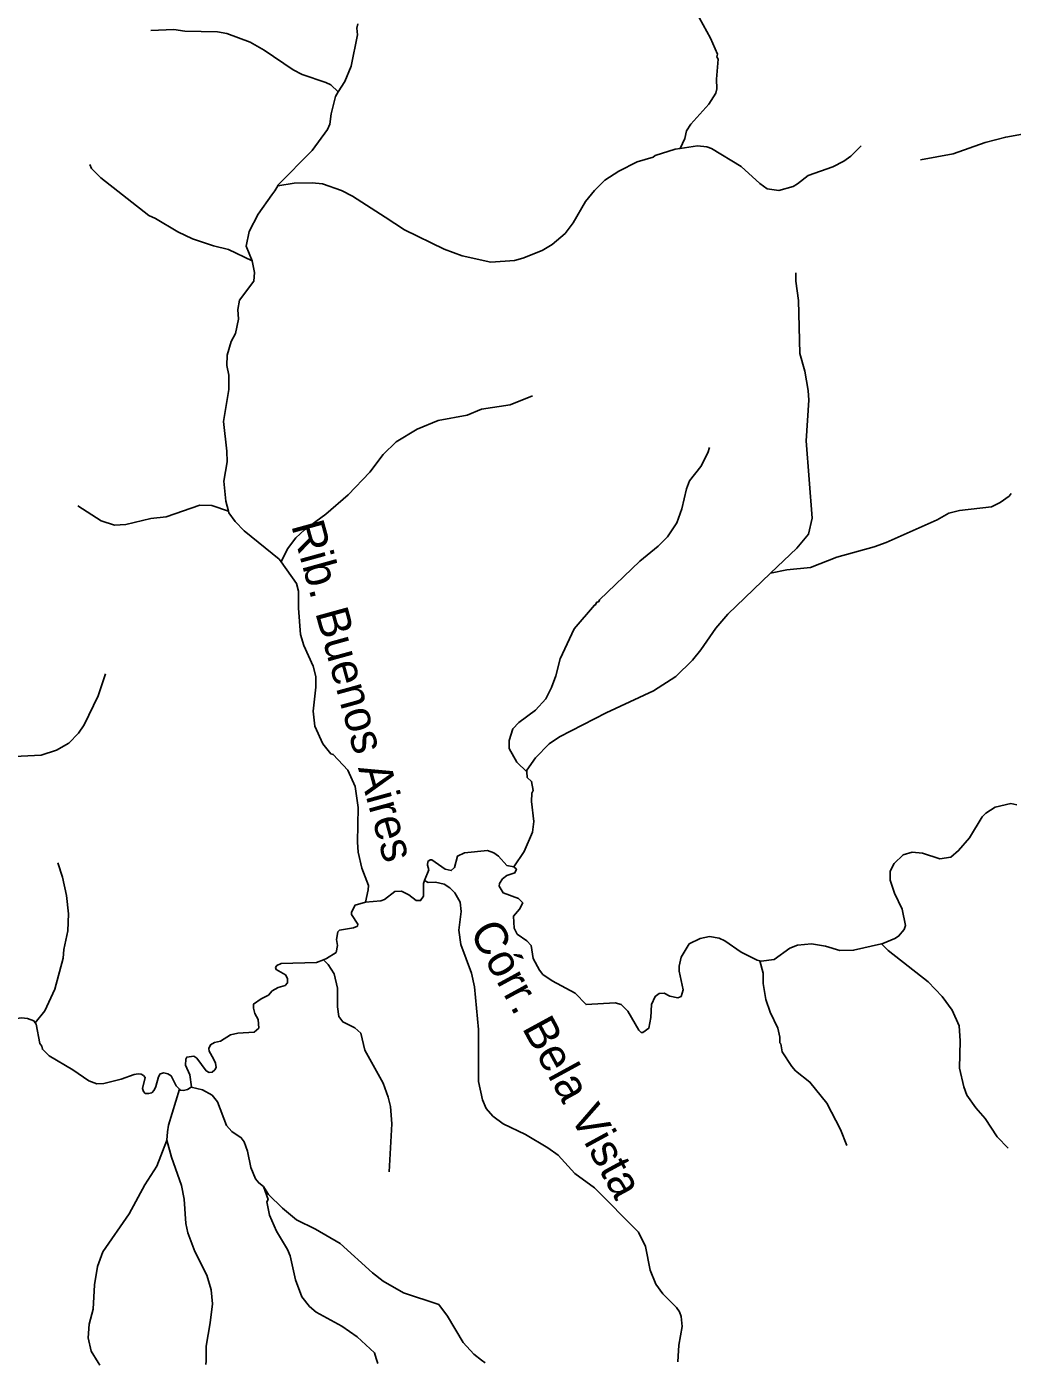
# Model space of a CAD drawing. Extents: x 280.4 to 335.6, y 8893.9 to 8949.5.
# Drawn here: x 288.06 to 294.07, y 8893.97 to 8902.11 of the extents above; entities that cross this region are included whole.
import ezdxf
from ezdxf.enums import TextEntityAlignment as Align

# ---------------------------------------------------------------- set-up
doc = ezdxf.new("R2010")
doc.units = 0
doc.header["$LTSCALE"] = 0.064
doc.layers.add('61', color=7, linetype='Continuous')
doc.layers.add('7', color=7, linetype='Continuous', lineweight=25)

msp = doc.modelspace()

# ---------------------------------------------------------------- linework, layer by layer
at = {"layer": '7'}
for points in [[(292.1026, 8902.3635), (292.1381, 8902.2072), (292.2287, 8902.0446), (292.2702, 8901.9485), (292.2673, 8901.9318), (292.2752, 8901.9178), (292.2642, 8901.7959), (292.2672, 8901.7361), (292.2606, 8901.7107), (292.2176, 8901.6432), (292.1079, 8901.5207), (292.0823, 8901.4806), (292.0711, 8901.4353), (292.0427, 8901.374)], [(290.0785, 8902.132), (290.0737, 8902.1062), (290.0781, 8902.0646), (290.0394, 8901.8751), (290.0003, 8901.7808), (289.96, 8901.718)], [(288.8188, 8902.0924), (288.9593, 8902.0974), (289.0246, 8902.0879), (289.2238, 8902.0829), (289.2805, 8902.0732), (289.4237, 8902.0206), (289.5095, 8901.9715), (289.6843, 8901.8535), (289.7411, 8901.8237), (289.885, 8901.7757), (289.9143, 8901.7605), (289.96, 8901.718)], [(289.96, 8901.718), (289.9426, 8901.691), (289.9167, 8901.5856), (289.9084, 8901.5209), (289.8939, 8901.4882), (289.8002, 8901.361), (289.5925, 8901.1493), (289.5911, 8901.1461)], [(293.5062, 8901.3053), (293.7072, 8901.3412), (293.9017, 8901.4091), (294.0265, 8901.4433), (294.1731, 8901.4679)], [(292.0427, 8901.374), (292.0132, 8901.3699), (291.8904, 8901.33), (291.8794, 8901.3204), (291.781, 8901.2914), (291.6685, 8901.2353), (291.585, 8901.1814), (291.5205, 8901.1171), (291.4672, 8901.0509), (291.3904, 8900.9214), (291.3428, 8900.8565), (291.2642, 8900.7884), (291.2027, 8900.7528), (291.0837, 8900.7054), (291.0333, 8900.6919), (290.8895, 8900.6821), (290.7152, 8900.7191), (290.605, 8900.7601), (290.3641, 8900.8791), (290.2452, 8900.9555), (290.0465, 8901.0831), (289.9803, 8901.1187), (289.8644, 8901.1587), (289.801, 8901.1651), (289.6917, 8901.1617), (289.5911, 8901.1461)], [(293.1458, 8901.3899), (293.0836, 8901.3274), (293.0397, 8901.2954), (292.9724, 8901.262), (292.8229, 8901.21), (292.7587, 8901.1575), (292.7317, 8901.143), (292.6446, 8901.1173), (292.5739, 8901.1273), (292.5288, 8901.1606), (292.415, 8901.2638), (292.2345, 8901.3731), (292.2048, 8901.3828), (292.1489, 8901.3889), (292.0427, 8901.374)], [(288.4457, 8901.2761), (288.4572, 8901.2525), (288.5135, 8901.1949), (288.805, 8900.9653), (288.8457, 8900.9479), (288.9818, 8900.8667), (289.0727, 8900.8245), (289.2003, 8900.7805), (289.2921, 8900.7578), (289.4346, 8900.6905)], [(289.5911, 8901.1461), (289.5731, 8901.1158), (289.5552, 8901.0912), (289.4719, 8900.9745), (289.4174, 8900.8676), (289.3984, 8900.7798), (289.4346, 8900.6905)], [(289.4346, 8900.6905), (289.4502, 8900.6189), (289.4458, 8900.5657), (289.3584, 8900.4501), (289.3472, 8900.3942), (289.3517, 8900.3351), (289.3348, 8900.2468), (289.3082, 8900.1977), (289.283, 8900.1143), (289.2815, 8900.0513), (289.2926, 8899.9937), (289.2942, 8899.9064), (289.2606, 8899.7122), (289.2814, 8899.5314), (289.2829, 8899.4667), (289.2639, 8899.3483), (289.2751, 8899.2267), (289.291, 8899.1653)], [(292.7486, 8900.617), (292.7471, 8900.565), (292.763, 8900.4486), (292.7712, 8900.1256), (292.8031, 8900.0175), (292.8235, 8899.9), (292.8269, 8899.8416), (292.8111, 8899.593), (292.8462, 8899.1219), (292.8256, 8899.0261), (292.7537, 8898.9409), (292.5936, 8898.7874)], [(291.1433, 8899.8671), (291.0083, 8899.8125), (290.8333, 8899.7854), (290.7463, 8899.75), (290.5681, 8899.7175), (290.441, 8899.6649), (290.3136, 8899.587), (290.2331, 8899.5098), (290.1525, 8899.4037), (290.0203, 8899.2652), (289.8851, 8899.1469), (289.7551, 8899.0513), (289.7016, 8899.0024), (289.6513, 8898.9364), (289.6117, 8898.8573)], [(292.2218, 8899.5529), (292.2122, 8899.5202), (292.1687, 8899.4379), (292.1007, 8899.3509), (292.0813, 8899.3018), (292.0529, 8899.1789), (292.0231, 8899.094), (291.9655, 8899.0098), (291.908, 8898.9523), (291.7966, 8898.86), (291.5506, 8898.6248), (291.547, 8898.6153), (291.5342, 8898.61), (291.5282, 8898.5955), (291.5208, 8898.5936), (291.3963, 8898.4479), (291.3127, 8898.2672), (291.2858, 8898.1633), (291.26, 8898.092), (291.2238, 8898.0225), (291.1615, 8897.9533), (291.0605, 8897.8791), (291.0245, 8897.8398), (291.0009, 8897.769), (291.0008, 8897.7195), (291.0483, 8897.6375), (291.1086, 8897.5779)], [(294.0587, 8899.2729), (294.0474, 8899.2571), (293.9934, 8899.2175), (293.9391, 8899.1909), (293.7456, 8899.1692), (293.6796, 8899.153), (293.6085, 8899.113), (293.2989, 8898.9751), (293.2242, 8898.9477), (292.9965, 8898.8861), (292.8371, 8898.8222), (292.692, 8898.8081), (292.5936, 8898.7874)], [(288.3732, 8899.1969), (288.5149, 8899.1056), (288.596, 8899.0797), (288.6657, 8899.0845), (288.8186, 8899.121), (288.912, 8899.1309), (289.1175, 8899.2011), (289.19, 8899.2005), (289.291, 8899.1653)], [(289.291, 8899.1653), (289.2939, 8899.1542), (289.3313, 8899.1018), (289.3868, 8899.0464), (289.5999, 8898.8738), (289.6117, 8898.8573)], [(289.6117, 8898.8573), (289.7055, 8898.7258), (289.7175, 8898.6789), (289.7181, 8898.5742), (289.7309, 8898.4144), (289.7511, 8898.3475), (289.8066, 8898.2208), (289.8235, 8898.1577), (289.8234, 8898.0938), (289.8077, 8897.9473), (289.8183, 8897.8562), (289.8664, 8897.7494), (289.9152, 8897.6884), (289.9289, 8897.6833), (290.0183, 8897.5886), (290.0638, 8897.4883)], [(292.5936, 8898.7874), (292.3344, 8898.539), (292.2613, 8898.4533), (292.1691, 8898.3214), (292.1174, 8898.2583), (292.0171, 8898.1582), (291.8802, 8898.0706), (291.5923, 8897.9377), (291.3071, 8897.7905), (291.2457, 8897.7479), (291.1616, 8897.6639), (291.1082, 8897.5875), (291.1086, 8897.5779)], [(288.541, 8898.1756), (288.4966, 8898.0414), (288.4129, 8897.8643), (288.3765, 8897.8128), (288.3176, 8897.7531), (288.2442, 8897.711), (288.1491, 8897.6791), (287.9876, 8897.6723), (287.923, 8897.6592), (287.7644, 8897.5751), (287.6662, 8897.5355), (287.6053, 8897.502), (287.5146, 8897.4319)], [(291.1086, 8897.5779), (291.1099, 8897.5441), (291.1379, 8897.5199), (291.1473, 8897.4641), (291.1385, 8897.4477), (291.1367, 8897.398), (291.1508, 8897.2753), (291.1444, 8897.2118), (291.092, 8897.0939), (291.0298, 8897.0005)], [(290.0638, 8897.4883), (290.081, 8897.362), (290.0763, 8897.1502), (290.0823, 8897.0898), (290.103, 8896.9926), (290.1434, 8896.8855), (290.1429, 8896.8602), (290.1253, 8896.7855)], [(294.0943, 8897.3777), (294.0566, 8897.3844), (293.962, 8897.3639), (293.9056, 8897.3272), (293.8826, 8897.3044), (293.8066, 8897.1769), (293.739, 8897.0987), (293.6921, 8897.0583), (293.6258, 8897.0487), (293.5203, 8897.0839), (293.4572, 8897.0901), (293.4023, 8897.0737), (293.3468, 8897.0198), (293.3229, 8896.9727), (293.3231, 8896.9192), (293.3488, 8896.8402), (293.3963, 8896.7415), (293.4156, 8896.6425)], [(291.0298, 8897.0005), (290.9879, 8897.0072), (290.9353, 8897.064), (290.9072, 8897.0856), (290.8701, 8897.0996), (290.7283, 8897.0842), (290.6861, 8897.0643), (290.668, 8896.9963), (290.6482, 8896.9769), (290.6112, 8896.9861), (290.5311, 8897.0432), (290.5197, 8897.0428), (290.5065, 8897.0317), (290.5035, 8897.0103), (290.511, 8896.9807), (290.4854, 8896.916)], [(288.252, 8897.0248), (288.2805, 8896.9359), (288.3041, 8896.8253), (288.317, 8896.7134), (288.3122, 8896.611), (288.2888, 8896.4966), (288.2849, 8896.4427), (288.2334, 8896.254), (288.173, 8896.1227), (288.1132, 8896.0501)], [(292.5286, 8896.4278), (292.5128, 8896.4313), (292.4143, 8896.4801), (292.3152, 8896.5495), (292.2807, 8896.5653), (292.2224, 8896.5752), (292.1656, 8896.5642), (292.0978, 8896.5303), (292.0496, 8896.4497), (292.0373, 8896.3944), (292.037, 8896.3649), (292.0623, 8896.2505), (292.0489, 8896.2104), (292.0298, 8896.2027), (291.981, 8896.2118), (291.945, 8896.2296), (291.9155, 8896.2278), (291.8905, 8896.2109), (291.8677, 8896.1609), (291.8638, 8896.0815), (291.8517, 8896.0168), (291.8157, 8895.9914), (291.8061, 8895.9905), (291.7902, 8896.0049), (291.7234, 8896.121), (291.6844, 8896.1612), (291.6465, 8896.1722), (291.4695, 8896.1613), (291.4026, 8896.2303), (291.2623, 8896.3053), (291.2072, 8896.3435), (291.1858, 8896.3704), (291.1484, 8896.4425), (291.135, 8896.5216), (291.1084, 8896.5488), (291.0508, 8896.5908), (291.031, 8896.6271), (291.0267, 8896.6988), (291.0634, 8896.7422), (291.0835, 8896.7815), (291.0588, 8896.8073), (290.9656, 8896.8408), (290.9401, 8896.8815), (290.9419, 8896.8987), (290.9613, 8896.9275), (290.9863, 8896.9461), (291.0365, 8896.963), (291.0459, 8896.9847), (291.0298, 8897.0005)], [(290.4854, 8896.916), (290.4785, 8896.8986), (290.4794, 8896.8215), (290.4613, 8896.7947), (290.4339, 8896.7941), (290.3902, 8896.8298), (290.3443, 8896.8516), (290.3052, 8896.8493), (290.2425, 8896.8001), (290.2193, 8896.7927), (290.1253, 8896.7855)], [(292.0297, 8893.9855), (292.0312, 8894.0204), (292.0341, 8894.0883), (292.056, 8894.2019), (292.0492, 8894.261), (292.0395, 8894.2894), (292.0209, 8894.3171), (291.9374, 8894.3992), (291.8947, 8894.4578), (291.8597, 8894.5434), (291.8319, 8894.6887), (291.7901, 8894.775), (291.5204, 8895.0463), (291.4015, 8895.1332), (291.2991, 8895.2435), (291.2358, 8895.2888), (291.0998, 8895.37), (290.9655, 8895.4343), (290.902, 8895.4825), (290.8614, 8895.5284), (290.8395, 8895.5815), (290.8152, 8895.6932), (290.815, 8896.0097), (290.7909, 8896.2697), (290.7724, 8896.353), (290.7064, 8896.5273), (290.6937, 8896.6142), (290.7095, 8896.7271), (290.7032, 8896.7856), (290.6712, 8896.8406), (290.6397, 8896.8721), (290.6044, 8896.8947), (290.5521, 8896.9062), (290.5075, 8896.905), (290.4854, 8896.916)], [(290.1253, 8896.7855), (290.0634, 8896.7664), (290.0415, 8896.7231), (290.0411, 8896.7093), (290.0784, 8896.6504), (290.0765, 8896.6387), (290.0531, 8896.6279), (289.9682, 8896.6135), (289.9573, 8896.6032), (289.9486, 8896.5577), (289.9546, 8896.5201), (289.9475, 8896.4788), (289.889, 8896.4418), (289.8693, 8896.434)], [(293.4156, 8896.6425), (293.4081, 8896.6173), (293.3741, 8896.5775), (293.3515, 8896.5625), (293.2773, 8896.5322), (293.27, 8896.5305)], [(293.27, 8896.5305), (293.0992, 8896.4919), (293.015, 8896.4906), (292.9277, 8896.5164), (292.8437, 8896.5303), (292.7582, 8896.5226), (292.7121, 8896.5047), (292.6165, 8896.4365), (292.5375, 8896.4259), (292.5286, 8896.4278)], [(294.0421, 8895.2861), (293.9741, 8895.356), (293.9021, 8895.468), (293.8436, 8895.5318), (293.7904, 8895.6099), (293.7705, 8895.6611), (293.7451, 8895.773), (293.7498, 8895.9402), (293.7433, 8896.0308), (293.6994, 8896.1271), (293.639, 8896.2109), (293.5536, 8896.2996), (293.3106, 8896.49), (293.27, 8896.5305)], [(289.8693, 8896.434), (289.8267, 8896.417), (289.6132, 8896.4104), (289.5863, 8896.3988), (289.578, 8896.386)], [(290.271, 8895.143), (290.2874, 8895.4341), (290.2774, 8895.5404), (290.2649, 8895.5964), (290.2327, 8895.6835), (290.1227, 8895.8844), (290.0981, 8895.987), (290.0607, 8896.0197), (289.987, 8896.0558), (289.9644, 8896.0884), (289.9548, 8896.1474), (289.9547, 8896.2617), (289.9356, 8896.3474), (289.8979, 8896.4061), (289.8693, 8896.434)], [(293.0576, 8895.3036), (293.0192, 8895.4007), (292.9356, 8895.5612), (292.8336, 8895.6887), (292.7464, 8895.7573), (292.7225, 8895.7832), (292.6647, 8895.8729), (292.6558, 8895.922), (292.6497, 8895.9278), (292.651, 8895.9628), (292.6373, 8896.0165), (292.5916, 8896.1158), (292.5645, 8896.1927), (292.5489, 8896.2891), (292.5484, 8896.352), (292.5286, 8896.4278)], [(289.578, 8896.386), (289.5823, 8896.3741), (289.638, 8896.3431), (289.6506, 8896.3209), (289.6507, 8896.2928), (289.6362, 8896.2764), (289.5941, 8896.2651), (289.5583, 8896.2458), (289.5344, 8896.2176), (289.4894, 8896.1967), (289.4437, 8896.1644), (289.4432, 8896.1395), (289.4523, 8896.1059), (289.4717, 8896.0696), (289.4755, 8896.0175), (289.4476, 8895.9929), (289.3478, 8895.9867), (289.3039, 8895.9764), (289.2421, 8895.9392), (289.2063, 8895.9306), (289.1825, 8895.9162), (289.1715, 8895.8935), (289.1738, 8895.877), (289.2005, 8895.8315), (289.2126, 8895.8037), (289.2156, 8895.778), (289.2077, 8895.7638), (289.1917, 8895.7502), (289.1734, 8895.747), (289.1553, 8895.757), (289.0978, 8895.8358), (289.0801, 8895.847), (289.037, 8895.8409), (289.0305, 8895.8282), (289.0289, 8895.7931), (289.056, 8895.7333), (289.0665, 8895.6605), (289.0636, 8895.6586)], [(288.1132, 8896.0501), (288.1045, 8896.063), (288.0677, 8896.0768), (288.0305, 8896.0797), (287.9877, 8896.0733), (287.9641, 8896.0587), (287.9245, 8896.0635), (287.9128, 8896.089), (287.9188, 8896.118), (287.9169, 8896.1608), (287.8773, 8896.1796), (287.8534, 8896.1738), (287.8286, 8896.1385), (287.7874, 8895.9854), (287.7644, 8895.9708), (287.7367, 8895.9722), (287.7246, 8895.9817), (287.6819, 8895.9764), (287.6764, 8895.9703)], [(288.9922, 8895.6464), (288.972, 8895.6669), (288.9411, 8895.727), (288.9215, 8895.7404), (288.8968, 8895.7454), (288.876, 8895.7387), (288.8641, 8895.7204), (288.8486, 8895.662), (288.8385, 8895.6404), (288.8237, 8895.6239), (288.8045, 8895.6191), (288.7842, 8895.6207), (288.7725, 8895.6327), (288.7672, 8895.6503), (288.784, 8895.7167), (288.7744, 8895.7289), (288.7599, 8895.7369), (288.7404, 8895.7395), (288.7165, 8895.7357), (288.6376, 8895.7073), (288.5316, 8895.6809), (288.4883, 8895.6782), (288.4409, 8895.697), (288.3422, 8895.7642), (288.1982, 8895.8489), (288.1578, 8895.8892), (288.1535, 8895.9086), (288.1414, 8895.9245), (288.1194, 8896.0409), (288.1132, 8896.0501)], [(288.9155, 8895.3346), (288.9192, 8895.3869), (288.9256, 8895.4267), (288.9922, 8895.6464)], [(289.0636, 8895.6586), (289.0411, 8895.644), (289.0165, 8895.638), (288.9979, 8895.6406), (288.9922, 8895.6464)], [(289.505, 8895.0532), (289.4754, 8895.0757), (289.456, 8895.1), (289.4271, 8895.1687), (289.4079, 8895.2695), (289.386, 8895.3262), (289.3695, 8895.3499), (289.3119, 8895.3886), (289.2795, 8895.4257), (289.2249, 8895.5696), (289.1914, 8895.6097), (289.1331, 8895.6426), (289.0636, 8895.6586)], [(288.5075, 8893.9652), (288.4972, 8893.9821), (288.4549, 8894.0518), (288.4354, 8894.1326), (288.442, 8894.2146), (288.4673, 8894.3074), (288.4741, 8894.4541), (288.4933, 8894.5672), (288.5249, 8894.6555), (288.6859, 8894.8862), (288.7812, 8895.063), (288.8541, 8895.1768), (288.9145, 8895.3295), (288.9155, 8895.3346)], [(289.1541, 8893.9689), (289.1543, 8893.9928), (289.1552, 8894.0803), (289.1803, 8894.2228), (289.1932, 8894.3387), (289.1857, 8894.4243), (289.1596, 8894.5128), (289.0861, 8894.6568), (289.0434, 8894.7705), (289.0305, 8894.8281), (289.0203, 8894.977), (289.0047, 8895.0591), (288.9443, 8895.2311), (288.9155, 8895.3346)], [(290.2004, 8893.975), (290.1912, 8894.006), (290.1808, 8894.0412), (290.0743, 8894.1388), (289.9826, 8894.2031), (289.8249, 8894.2889), (289.7853, 8894.3235), (289.7382, 8894.3814), (289.6991, 8894.4858), (289.6668, 8894.6305), (289.65, 8894.6704), (289.5847, 8894.7819), (289.5411, 8894.8783), (289.5248, 8894.9597), (289.532, 8894.9752), (289.505, 8895.0532)], [(290.8559, 8893.9788), (290.8329, 8893.9966), (290.7864, 8894.0325), (290.7204, 8894.1032), (290.6259, 8894.2633), (290.5724, 8894.334), (290.3585, 8894.4064), (290.233, 8894.4776), (290.1682, 8894.5286), (289.9707, 8894.7072), (289.8219, 8894.7944), (289.7053, 8894.8513), (289.621, 8894.921), (289.5355, 8895.0057), (289.505, 8895.0532)]]:
    msp.add_lwpolyline(points, dxfattribs=at)

# ---------------------------------------------------------------- texts
at = {"layer": '61'}
for s, rotation, p in [('Rib. Buenos Aires', 285.422, (289.9571, 8898.0467)), ('Córr. Bela Vista', 298.571, (291.2047, 8895.784))]:
    msp.add_text(s, height=0.2, rotation=rotation, dxfattribs=at).set_placement(p, align=Align.CENTER)

doc.saveas('drawing.dxf')
